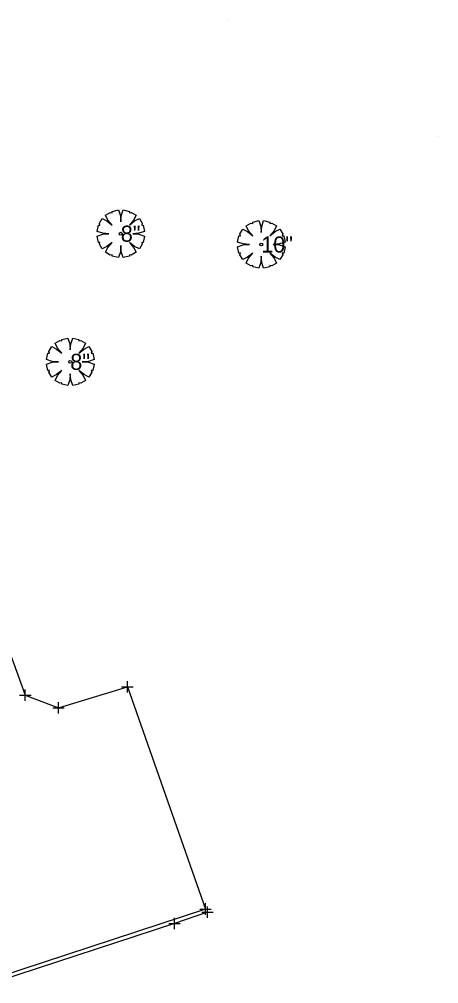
# Model space of a CAD drawing. Extents: x 1729655 to 1739338, y 463812 to 469501.
# Drawn here: x 1735072.1 to 1735118.8, y 466921 to 467028.6 of the extents above; entities that cross this region are included whole.
import ezdxf

# ---------------------------------------------------------------- set-up
doc = ezdxf.new("R2010")
doc.units = 0
for name, color, linetype in [('Default', 7, 'Continuous'), ('S_Bridge_Column_Round', 7, 'Continuous'), ('S_Curb_Type_5', 7, 'Continuous'), ('S_Ground_SpotElevation', 7, 'Continuous'), ('S_Terrain_High_Points', 7, 'Continuous'), ('S_Utilities_UG_Sanitary_MH', 7, 'Continuous')]:
    doc.layers.add(name, color=color, linetype=linetype)

msp = doc.modelspace()

# ---------------------------------------------------------------- linework, layer by layer
at = {"layer": 'Default'}
for p, q in [((1735095.33, 467028.58), (1735095.33, 467028.58)), ((1735118.8, 467015.54), (1735118.8, 467015.54))]:
    msp.add_line(p, q, dxfattribs=at)
at = {"layer": 'S_Bridge_Column_Round'}
for p, q in [((1735084.11, 466953.47), (1735084.11, 466954.74)), ((1735072.74, 466952.55), (1735072.74, 466953.82)), ((1735083.47, 466954.11), (1735084.75, 466954.11)), ((1735084.11, 466954.11), (1735084.11, 466954.11)), ((1735072.1, 466953.18), (1735073.38, 466953.19)), ((1735072.74, 466953.19), (1735072.74, 466953.19)), ((1735076.44, 466951.15), (1735076.44, 466952.42)), ((1735075.8, 466951.78), (1735077.08, 466951.79)), ((1735076.44, 466951.79), (1735076.44, 466951.79)), ((1735092.82, 466928.69), (1735092.82, 466929.97)), ((1735092.18, 466929.33), (1735093.46, 466929.33)), ((1735092.4, 466928.98), (1735093.68, 466928.98)), ((1735092.82, 466929.33), (1735092.82, 466929.33)), ((1735093.04, 466928.34), (1735093.04, 466929.62)), ((1735093.04, 466928.98), (1735093.04, 466928.98)), ((1735088.72, 466927.72), (1735089.99, 466927.72)), ((1735089.35, 466927.08), (1735089.35, 466928.36)), ((1735089.35, 466927.72), (1735089.35, 466927.72))]:
    msp.add_line(p, q, dxfattribs=at)
at = {"layer": 'S_Curb_Type_5'}
for points in [[(1735082.05, 467004.66), (1735081.36, 467004.71), (1735080.73, 467004.92), (1735080.89, 467005.61), (1735081.05, 467005.61), (1735080.99, 467005.82), (1735081.31, 467006.35), (1735081.84, 467006.09), (1735082.43, 467005.61), (1735081.95, 467006.19), (1735081.68, 467006.72), (1735082.21, 467007.04), (1735082.43, 467006.99), (1735082.43, 467007.15), (1735083.11, 467007.31), (1735083.33, 467006.67), (1735083.38, 467005.98), (1735083.43, 467006.67), (1735083.64, 467007.31), (1735084.34, 467007.15), (1735084.34, 467006.99), (1735084.55, 467007.04), (1735085.08, 467006.72), (1735084.81, 467006.19), (1735084.34, 467005.61), (1735084.92, 467006.09), (1735085.45, 467006.35), (1735085.77, 467005.82), (1735085.71, 467005.61), (1735085.87, 467005.61), (1735086.03, 467004.92), (1735085.4, 467004.71), (1735084.71, 467004.66), (1735085.4, 467004.6), (1735086.03, 467004.39), (1735085.87, 467003.7), (1735085.71, 467003.7), (1735085.77, 467003.49), (1735085.45, 467002.96), (1735084.92, 467003.22), (1735084.34, 467003.7), (1735084.81, 467003.12), (1735085.08, 467002.59), (1735084.55, 467002.27), (1735084.34, 467002.32), (1735084.34, 467002.16), (1735083.64, 467002), (1735083.43, 467002.64), (1735083.38, 467003.33), (1735083.33, 467002.64), (1735083.11, 467002), (1735082.43, 467002.16), (1735082.43, 467002.32), (1735082.21, 467002.27), (1735081.68, 467002.59), (1735081.95, 467003.12), (1735082.43, 467003.7), (1735081.84, 467003.22), (1735081.31, 467002.96), (1735080.99, 467003.49), (1735081.05, 467003.7), (1735080.89, 467003.7), (1735080.73, 467004.39), (1735081.36, 467004.6), (1735082.05, 467004.66)], [(1735097.71, 467003.46), (1735097.02, 467003.52), (1735096.38, 467003.73), (1735096.54, 467004.42), (1735096.7, 467004.42), (1735096.65, 467004.63), (1735096.96, 467005.16), (1735097.49, 467004.9), (1735098.08, 467004.42), (1735097.6, 467005), (1735097.34, 467005.53), (1735097.87, 467005.85), (1735098.08, 467005.8), (1735098.08, 467005.96), (1735098.77, 467006.12), (1735098.98, 467005.48), (1735099.03, 467004.79), (1735099.09, 467005.48), (1735099.3, 467006.12), (1735099.99, 467005.96), (1735099.99, 467005.8), (1735100.2, 467005.85), (1735100.73, 467005.53), (1735100.46, 467005), (1735099.99, 467004.42), (1735100.57, 467004.9), (1735101.1, 467005.16), (1735101.42, 467004.63), (1735101.37, 467004.42), (1735101.53, 467004.42), (1735101.69, 467003.73), (1735101.05, 467003.52), (1735100.36, 467003.46), (1735101.05, 467003.41), (1735101.69, 467003.2), (1735101.53, 467002.51), (1735101.37, 467002.51), (1735101.42, 467002.3), (1735101.1, 467001.77), (1735100.57, 467002.03), (1735099.99, 467002.51), (1735100.46, 467001.92), (1735100.73, 467001.39), (1735100.2, 467001.08), (1735099.99, 467001.13), (1735099.99, 467000.97), (1735099.3, 467000.81), (1735099.09, 467001.45), (1735099.03, 467002.14), (1735098.98, 467001.45), (1735098.77, 467000.81), (1735098.08, 467000.97), (1735098.08, 467001.13), (1735097.87, 467001.08), (1735097.34, 467001.39), (1735097.6, 467001.92), (1735098.08, 467002.51), (1735097.49, 467002.03), (1735096.96, 467001.77), (1735096.65, 467002.3), (1735096.7, 467002.51), (1735096.54, 467002.51), (1735096.38, 467003.2), (1735097.02, 467003.41), (1735097.71, 467003.46)], [(1735076.43, 466990.37), (1735075.74, 466990.42), (1735075.1, 466990.63), (1735075.26, 466991.32), (1735075.42, 466991.32), (1735075.37, 466991.54), (1735075.69, 466992.07), (1735076.22, 466991.8), (1735076.8, 466991.32), (1735076.32, 466991.91), (1735076.06, 466992.44), (1735076.59, 466992.76), (1735076.8, 466992.7), (1735076.8, 466992.86), (1735077.49, 466993.02), (1735077.7, 466992.38), (1735077.75, 466991.7), (1735077.81, 466992.38), (1735078.02, 466993.02), (1735078.71, 466992.86), (1735078.71, 466992.7), (1735078.92, 466992.76), (1735079.45, 466992.44), (1735079.19, 466991.91), (1735078.71, 466991.32), (1735079.29, 466991.8), (1735079.82, 466992.07), (1735080.14, 466991.54), (1735080.09, 466991.32), (1735080.25, 466991.32), (1735080.41, 466990.63), (1735079.77, 466990.42), (1735079.08, 466990.37), (1735079.77, 466990.32), (1735080.41, 466990.1), (1735080.25, 466989.41), (1735080.09, 466989.41), (1735080.14, 466989.2), (1735079.82, 466988.67), (1735079.29, 466988.94), (1735078.71, 466989.41), (1735079.19, 466988.83), (1735079.45, 466988.3), (1735078.92, 466987.98), (1735078.71, 466988.04), (1735078.71, 466987.88), (1735078.02, 466987.72), (1735077.81, 466988.35), (1735077.75, 466989.04), (1735077.7, 466988.35), (1735077.49, 466987.72), (1735076.8, 466987.88), (1735076.8, 466988.04), (1735076.59, 466987.98), (1735076.06, 466988.3), (1735076.32, 466988.83), (1735076.8, 466989.41), (1735076.22, 466988.94), (1735075.69, 466988.67), (1735075.37, 466989.2), (1735075.42, 466989.41), (1735075.26, 466989.41), (1735075.1, 466990.1), (1735075.74, 466990.32), (1735076.43, 466990.37)]]:
    msp.add_lwpolyline(points, dxfattribs=at)
for centre in [(1735083.38, 467004.66), (1735099.03, 467003.46), (1735077.75, 466990.37)]:
    msp.add_circle(centre, 0.166, dxfattribs=at)
at = {"layer": 'S_Ground_SpotElevation'}
for p, q in [((1735067.78, 466966.76), (1735072.74, 466953.19)), ((1735076.44, 466951.79), (1735084.11, 466954.11)), ((1735084.11, 466954.11), (1735092.82, 466929.33)), ((1735072.74, 466953.19), (1735076.44, 466951.79)), ((1735092.82, 466929.33), (1735062.66, 466919.39))]:
    msp.add_line(p, q, dxfattribs=at)
at = {"layer": 'S_Utilities_UG_Sanitary_MH'}
for p, q in [((1735093.04, 466928.98), (1735089.35, 466927.72)), ((1735089.35, 466927.72), (1735062.83, 466919.04))]:
    msp.add_line(p, q, dxfattribs=at)

# ---------------------------------------------------------------- texts
at = {"layer": 'S_Terrain_High_Points'}
for s, p in [('8"', (1735083.38, 467003.76)), ('10"', (1735099.03, 467002.56)), ('8"', (1735077.75, 466989.47))]:
    msp.add_text(s, height=1.8, dxfattribs=at).set_placement(p)

doc.saveas('drawing.dxf')
